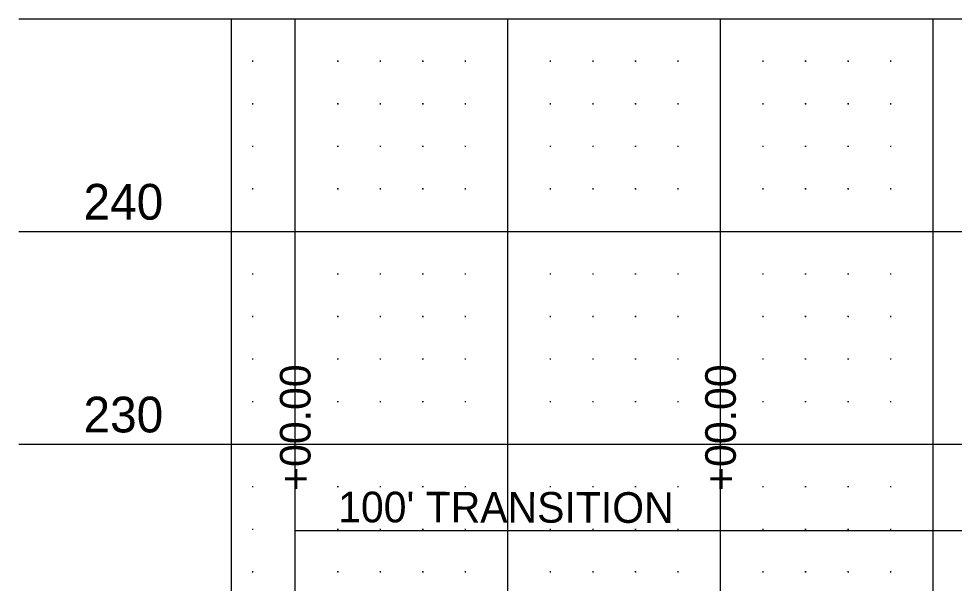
# Model space of a CAD drawing. Extents: x 471 to 2121, y 140 to 650.
# Drawn here: x 471.1 to 691, y 517.3 to 650 of the extents above; entities that cross this region are included whole.
import ezdxf

# ---------------------------------------------------------------- set-up
doc = ezdxf.new("R2010")
doc.units = 0
for name, color, linetype in [('DSN_DRFT_Border Grid', 7, 'Continuous'), ('DSN_RDWY_Prof Annotation', 7, 'Continuous'), ('Transition Dimensions', 7, 'Continuous')]:
    doc.layers.add(name, color=color, linetype=linetype)

msp = doc.modelspace()

# ---------------------------------------------------------------- linework, layer by layer
at = {"layer": 'DSN_DRFT_Border Grid'}
for p, q in [((471.06, 650), (521.06, 650)), ((521.06, 650), (2071.06, 650)), ((521.06, 150), (521.06, 650)), ((521.06, 650), (2071.06, 650)), ((521.06, 150), (521.06, 650)), ((536.06, 150), (536.06, 650)), ((536.06, 150), (536.06, 650)), ((586.06, 150), (586.06, 650)), ((586.06, 150), (586.06, 650)), ((636.06, 150), (636.06, 650)), ((636.06, 150), (636.06, 650)), ((686.06, 150), (686.06, 650)), ((686.06, 150), (686.06, 650)), ((526.18, 640), (525.94, 640)), ((526.18, 640), (525.94, 640)), ((526.06, 640.12), (526.06, 639.88)), ((526.06, 640.12), (526.06, 639.88)), ((546.18, 640), (545.94, 640)), ((546.18, 640), (545.94, 640)), ((546.06, 640.12), (546.06, 639.88)), ((546.06, 640.12), (546.06, 639.88)), ((556.18, 640), (555.94, 640)), ((556.18, 640), (555.94, 640)), ((556.06, 640.12), (556.06, 639.88)), ((556.06, 640.12), (556.06, 639.88)), ((566.18, 640), (565.94, 640)), ((566.18, 640), (565.94, 640)), ((566.06, 640.12), (566.06, 639.88)), ((566.06, 640.12), (566.06, 639.88)), ((576.18, 640), (575.94, 640)), ((576.18, 640), (575.94, 640)), ((576.06, 640.12), (576.06, 639.88)), ((576.06, 640.12), (576.06, 639.88)), ((596.18, 640), (595.94, 640)), ((596.18, 640), (595.94, 640)), ((596.06, 640.12), (596.06, 639.88)), ((596.06, 640.12), (596.06, 639.88)), ((606.18, 640), (605.94, 640)), ((606.18, 640), (605.94, 640)), ((606.06, 640.12), (606.06, 639.88)), ((606.06, 640.12), (606.06, 639.88)), ((616.18, 640), (615.94, 640)), ((616.18, 640), (615.94, 640)), ((616.06, 640.12), (616.06, 639.88)), ((616.06, 640.12), (616.06, 639.88)), ((626.18, 640), (625.94, 640)), ((626.18, 640), (625.94, 640)), ((626.06, 640.12), (626.06, 639.88)), ((626.06, 640.12), (626.06, 639.88)), ((646.18, 640), (645.94, 640)), ((646.18, 640), (645.94, 640)), ((646.06, 640.12), (646.06, 639.88)), ((646.06, 640.12), (646.06, 639.88)), ((656.18, 640), (655.94, 640)), ((656.18, 640), (655.94, 640)), ((656.06, 640.12), (656.06, 639.88)), ((656.06, 640.12), (656.06, 639.88)), ((666.18, 640), (665.94, 640)), ((666.18, 640), (665.94, 640)), ((666.06, 640.12), (666.06, 639.88)), ((666.06, 640.12), (666.06, 639.88)), ((676.18, 640), (675.94, 640)), ((676.18, 640), (675.94, 640)), ((676.06, 640.12), (676.06, 639.88)), ((676.06, 640.12), (676.06, 639.88)), ((526.18, 630), (525.94, 630)), ((526.18, 630), (525.94, 630)), ((526.06, 630.12), (526.06, 629.88)), ((526.06, 630.12), (526.06, 629.88)), ((546.18, 630), (545.94, 630)), ((546.18, 630), (545.94, 630)), ((546.06, 630.12), (546.06, 629.88)), ((546.06, 630.12), (546.06, 629.88)), ((556.18, 630), (555.94, 630)), ((556.18, 630), (555.94, 630)), ((556.06, 630.12), (556.06, 629.88)), ((556.06, 630.12), (556.06, 629.88)), ((566.18, 630), (565.94, 630)), ((566.18, 630), (565.94, 630)), ((566.06, 630.12), (566.06, 629.88)), ((566.06, 630.12), (566.06, 629.88)), ((576.18, 630), (575.94, 630)), ((576.18, 630), (575.94, 630)), ((576.06, 630.12), (576.06, 629.88)), ((576.06, 630.12), (576.06, 629.88)), ((596.18, 630), (595.94, 630)), ((596.18, 630), (595.94, 630)), ((596.06, 630.12), (596.06, 629.88)), ((596.06, 630.12), (596.06, 629.88)), ((606.18, 630), (605.94, 630)), ((606.18, 630), (605.94, 630)), ((606.06, 630.12), (606.06, 629.88)), ((606.06, 630.12), (606.06, 629.88)), ((616.18, 630), (615.94, 630)), ((616.18, 630), (615.94, 630)), ((616.06, 630.12), (616.06, 629.88)), ((616.06, 630.12), (616.06, 629.88)), ((626.18, 630), (625.94, 630)), ((626.18, 630), (625.94, 630)), ((626.06, 630.12), (626.06, 629.88)), ((626.06, 630.12), (626.06, 629.88)), ((646.18, 630), (645.94, 630)), ((646.18, 630), (645.94, 630)), ((646.06, 630.12), (646.06, 629.88)), ((646.06, 630.12), (646.06, 629.88)), ((656.18, 630), (655.94, 630)), ((656.18, 630), (655.94, 630)), ((656.06, 630.12), (656.06, 629.88)), ((656.06, 630.12), (656.06, 629.88)), ((666.18, 630), (665.94, 630)), ((666.18, 630), (665.94, 630)), ((666.06, 630.12), (666.06, 629.88)), ((666.06, 630.12), (666.06, 629.88)), ((676.18, 630), (675.94, 630)), ((676.18, 630), (675.94, 630)), ((676.06, 630.12), (676.06, 629.88)), ((676.06, 630.12), (676.06, 629.88)), ((526.18, 620), (525.94, 620)), ((526.18, 620), (525.94, 620)), ((526.06, 620.12), (526.06, 619.88)), ((526.06, 620.12), (526.06, 619.88)), ((546.18, 620), (545.94, 620)), ((546.18, 620), (545.94, 620)), ((546.06, 620.12), (546.06, 619.88)), ((546.06, 620.12), (546.06, 619.88)), ((556.18, 620), (555.94, 620)), ((556.18, 620), (555.94, 620)), ((556.06, 620.12), (556.06, 619.88)), ((556.06, 620.12), (556.06, 619.88)), ((566.18, 620), (565.94, 620)), ((566.18, 620), (565.94, 620)), ((566.06, 620.12), (566.06, 619.88)), ((566.06, 620.12), (566.06, 619.88)), ((576.18, 620), (575.94, 620)), ((576.18, 620), (575.94, 620)), ((576.06, 620.12), (576.06, 619.88)), ((576.06, 620.12), (576.06, 619.88)), ((596.18, 620), (595.94, 620)), ((596.18, 620), (595.94, 620)), ((596.06, 620.12), (596.06, 619.88)), ((596.06, 620.12), (596.06, 619.88)), ((606.18, 620), (605.94, 620)), ((606.18, 620), (605.94, 620)), ((606.06, 620.12), (606.06, 619.88)), ((606.06, 620.12), (606.06, 619.88)), ((616.18, 620), (615.94, 620)), ((616.18, 620), (615.94, 620)), ((616.06, 620.12), (616.06, 619.88)), ((616.06, 620.12), (616.06, 619.88)), ((626.18, 620), (625.94, 620)), ((626.18, 620), (625.94, 620)), ((626.06, 620.12), (626.06, 619.88)), ((626.06, 620.12), (626.06, 619.88)), ((646.18, 620), (645.94, 620)), ((646.18, 620), (645.94, 620)), ((646.06, 620.12), (646.06, 619.88)), ((646.06, 620.12), (646.06, 619.88)), ((656.18, 620), (655.94, 620)), ((656.18, 620), (655.94, 620)), ((656.06, 620.12), (656.06, 619.88)), ((656.06, 620.12), (656.06, 619.88)), ((666.18, 620), (665.94, 620)), ((666.18, 620), (665.94, 620)), ((666.06, 620.12), (666.06, 619.88)), ((666.06, 620.12), (666.06, 619.88)), ((676.18, 620), (675.94, 620)), ((676.18, 620), (675.94, 620)), ((676.06, 620.12), (676.06, 619.88)), ((676.06, 620.12), (676.06, 619.88)), ((526.18, 610), (525.94, 610)), ((526.18, 610), (525.94, 610)), ((526.06, 610.12), (526.06, 609.88)), ((526.06, 610.12), (526.06, 609.88)), ((546.18, 610), (545.94, 610)), ((546.18, 610), (545.94, 610)), ((546.06, 610.12), (546.06, 609.88)), ((546.06, 610.12), (546.06, 609.88)), ((556.18, 610), (555.94, 610)), ((556.18, 610), (555.94, 610)), ((556.06, 610.12), (556.06, 609.88)), ((556.06, 610.12), (556.06, 609.88)), ((566.18, 610), (565.94, 610)), ((566.18, 610), (565.94, 610)), ((566.06, 610.12), (566.06, 609.88)), ((566.06, 610.12), (566.06, 609.88)), ((576.18, 610), (575.94, 610)), ((576.18, 610), (575.94, 610)), ((576.06, 610.12), (576.06, 609.88)), ((576.06, 610.12), (576.06, 609.88)), ((596.18, 610), (595.94, 610)), ((596.18, 610), (595.94, 610)), ((596.06, 610.12), (596.06, 609.88)), ((596.06, 610.12), (596.06, 609.88)), ((606.18, 610), (605.94, 610)), ((606.18, 610), (605.94, 610)), ((606.06, 610.12), (606.06, 609.88)), ((606.06, 610.12), (606.06, 609.88)), ((616.18, 610), (615.94, 610)), ((616.18, 610), (615.94, 610)), ((616.06, 610.12), (616.06, 609.88)), ((616.06, 610.12), (616.06, 609.88)), ((626.18, 610), (625.94, 610)), ((626.18, 610), (625.94, 610)), ((626.06, 610.12), (626.06, 609.88)), ((626.06, 610.12), (626.06, 609.88)), ((646.18, 610), (645.94, 610)), ((646.18, 610), (645.94, 610)), ((646.06, 610.12), (646.06, 609.88)), ((646.06, 610.12), (646.06, 609.88)), ((656.18, 610), (655.94, 610)), ((656.18, 610), (655.94, 610)), ((656.06, 610.12), (656.06, 609.88)), ((656.06, 610.12), (656.06, 609.88)), ((666.18, 610), (665.94, 610)), ((666.18, 610), (665.94, 610)), ((666.06, 610.12), (666.06, 609.88)), ((666.06, 610.12), (666.06, 609.88)), ((676.18, 610), (675.94, 610)), ((676.18, 610), (675.94, 610)), ((676.06, 610.12), (676.06, 609.88)), ((676.06, 610.12), (676.06, 609.88)), ((471.06, 600), (521.06, 600)), ((521.06, 600), (2071.06, 600)), ((521.06, 600), (2071.06, 600)), ((526.18, 590), (525.94, 590)), ((526.18, 590), (525.94, 590)), ((526.06, 590.12), (526.06, 589.88)), ((526.06, 590.12), (526.06, 589.88)), ((546.18, 590), (545.94, 590)), ((546.18, 590), (545.94, 590)), ((546.06, 590.12), (546.06, 589.88)), ((546.06, 590.12), (546.06, 589.88)), ((556.18, 590), (555.94, 590)), ((556.18, 590), (555.94, 590)), ((556.06, 590.12), (556.06, 589.88)), ((556.06, 590.12), (556.06, 589.88)), ((566.18, 590), (565.94, 590)), ((566.18, 590), (565.94, 590)), ((566.06, 590.12), (566.06, 589.88)), ((566.06, 590.12), (566.06, 589.88)), ((576.18, 590), (575.94, 590)), ((576.18, 590), (575.94, 590)), ((576.06, 590.12), (576.06, 589.88)), ((576.06, 590.12), (576.06, 589.88)), ((596.18, 590), (595.94, 590)), ((596.18, 590), (595.94, 590)), ((596.06, 590.12), (596.06, 589.88)), ((596.06, 590.12), (596.06, 589.88)), ((606.18, 590), (605.94, 590)), ((606.18, 590), (605.94, 590)), ((606.06, 590.12), (606.06, 589.88)), ((606.06, 590.12), (606.06, 589.88)), ((616.18, 590), (615.94, 590)), ((616.18, 590), (615.94, 590)), ((616.06, 590.12), (616.06, 589.88)), ((616.06, 590.12), (616.06, 589.88)), ((626.18, 590), (625.94, 590)), ((626.18, 590), (625.94, 590)), ((626.06, 590.12), (626.06, 589.88)), ((626.06, 590.12), (626.06, 589.88)), ((646.18, 590), (645.94, 590)), ((646.18, 590), (645.94, 590)), ((646.06, 590.12), (646.06, 589.88)), ((646.06, 590.12), (646.06, 589.88)), ((656.18, 590), (655.94, 590)), ((656.18, 590), (655.94, 590)), ((656.06, 590.12), (656.06, 589.88)), ((656.06, 590.12), (656.06, 589.88)), ((666.18, 590), (665.94, 590)), ((666.18, 590), (665.94, 590)), ((666.06, 590.12), (666.06, 589.88)), ((666.06, 590.12), (666.06, 589.88)), ((676.18, 590), (675.94, 590)), ((676.18, 590), (675.94, 590)), ((676.06, 590.12), (676.06, 589.88)), ((676.06, 590.12), (676.06, 589.88)), ((526.18, 580), (525.94, 580)), ((526.18, 580), (525.94, 580)), ((526.06, 580.12), (526.06, 579.88)), ((526.06, 580.12), (526.06, 579.88)), ((546.18, 580), (545.94, 580)), ((546.18, 580), (545.94, 580)), ((546.06, 580.12), (546.06, 579.88)), ((546.06, 580.12), (546.06, 579.88)), ((556.18, 580), (555.94, 580)), ((556.18, 580), (555.94, 580)), ((556.06, 580.12), (556.06, 579.88)), ((556.06, 580.12), (556.06, 579.88)), ((566.18, 580), (565.94, 580)), ((566.18, 580), (565.94, 580)), ((566.06, 580.12), (566.06, 579.88)), ((566.06, 580.12), (566.06, 579.88)), ((576.18, 580), (575.94, 580)), ((576.18, 580), (575.94, 580)), ((576.06, 580.12), (576.06, 579.88)), ((576.06, 580.12), (576.06, 579.88)), ((596.18, 580), (595.94, 580)), ((596.18, 580), (595.94, 580)), ((596.06, 580.12), (596.06, 579.88)), ((596.06, 580.12), (596.06, 579.88)), ((606.18, 580), (605.94, 580)), ((606.18, 580), (605.94, 580)), ((606.06, 580.12), (606.06, 579.88)), ((606.06, 580.12), (606.06, 579.88)), ((616.18, 580), (615.94, 580)), ((616.18, 580), (615.94, 580)), ((616.06, 580.12), (616.06, 579.88)), ((616.06, 580.12), (616.06, 579.88)), ((626.18, 580), (625.94, 580)), ((626.18, 580), (625.94, 580)), ((626.06, 580.12), (626.06, 579.88)), ((626.06, 580.12), (626.06, 579.88)), ((646.18, 580), (645.94, 580)), ((646.18, 580), (645.94, 580)), ((646.06, 580.12), (646.06, 579.88)), ((646.06, 580.12), (646.06, 579.88)), ((656.18, 580), (655.94, 580)), ((656.18, 580), (655.94, 580)), ((656.06, 580.12), (656.06, 579.88)), ((656.06, 580.12), (656.06, 579.88)), ((666.18, 580), (665.94, 580)), ((666.18, 580), (665.94, 580)), ((666.06, 580.12), (666.06, 579.88)), ((666.06, 580.12), (666.06, 579.88)), ((676.18, 580), (675.94, 580)), ((676.18, 580), (675.94, 580)), ((676.06, 580.12), (676.06, 579.88)), ((676.06, 580.12), (676.06, 579.88)), ((526.18, 570), (525.94, 570)), ((526.18, 570), (525.94, 570)), ((526.06, 570.12), (526.06, 569.88)), ((526.06, 570.12), (526.06, 569.88)), ((546.18, 570), (545.94, 570)), ((546.18, 570), (545.94, 570)), ((546.06, 570.12), (546.06, 569.88)), ((546.06, 570.12), (546.06, 569.88)), ((556.18, 570), (555.94, 570)), ((556.18, 570), (555.94, 570)), ((556.06, 570.12), (556.06, 569.88)), ((556.06, 570.12), (556.06, 569.88)), ((566.18, 570), (565.94, 570)), ((566.18, 570), (565.94, 570)), ((566.06, 570.12), (566.06, 569.88)), ((566.06, 570.12), (566.06, 569.88)), ((576.18, 570), (575.94, 570)), ((576.18, 570), (575.94, 570)), ((576.06, 570.12), (576.06, 569.88)), ((576.06, 570.12), (576.06, 569.88)), ((596.18, 570), (595.94, 570)), ((596.18, 570), (595.94, 570)), ((596.06, 570.12), (596.06, 569.88)), ((596.06, 570.12), (596.06, 569.88)), ((606.18, 570), (605.94, 570)), ((606.18, 570), (605.94, 570)), ((606.06, 570.12), (606.06, 569.88)), ((606.06, 570.12), (606.06, 569.88)), ((616.18, 570), (615.94, 570)), ((616.18, 570), (615.94, 570)), ((616.06, 570.12), (616.06, 569.88)), ((616.06, 570.12), (616.06, 569.88)), ((626.18, 570), (625.94, 570)), ((626.18, 570), (625.94, 570)), ((626.06, 570.12), (626.06, 569.88)), ((626.06, 570.12), (626.06, 569.88)), ((646.18, 570), (645.94, 570)), ((646.18, 570), (645.94, 570)), ((646.06, 570.12), (646.06, 569.88)), ((646.06, 570.12), (646.06, 569.88)), ((656.18, 570), (655.94, 570)), ((656.18, 570), (655.94, 570)), ((656.06, 570.12), (656.06, 569.88)), ((656.06, 570.12), (656.06, 569.88)), ((666.18, 570), (665.94, 570)), ((666.18, 570), (665.94, 570)), ((666.06, 570.12), (666.06, 569.88)), ((666.06, 570.12), (666.06, 569.88)), ((676.18, 570), (675.94, 570)), ((676.18, 570), (675.94, 570)), ((676.06, 570.12), (676.06, 569.88)), ((676.06, 570.12), (676.06, 569.88)), ((526.18, 560), (525.94, 560)), ((526.18, 560), (525.94, 560)), ((526.06, 560.12), (526.06, 559.88)), ((526.06, 560.12), (526.06, 559.88)), ((546.18, 560), (545.94, 560)), ((546.18, 560), (545.94, 560)), ((546.06, 560.12), (546.06, 559.88)), ((546.06, 560.12), (546.06, 559.88)), ((556.18, 560), (555.94, 560)), ((556.18, 560), (555.94, 560)), ((556.06, 560.12), (556.06, 559.88)), ((556.06, 560.12), (556.06, 559.88)), ((566.18, 560), (565.94, 560)), ((566.18, 560), (565.94, 560)), ((566.06, 560.12), (566.06, 559.88)), ((566.06, 560.12), (566.06, 559.88)), ((576.18, 560), (575.94, 560)), ((576.18, 560), (575.94, 560)), ((576.06, 560.12), (576.06, 559.88)), ((576.06, 560.12), (576.06, 559.88)), ((596.18, 560), (595.94, 560)), ((596.18, 560), (595.94, 560)), ((596.06, 560.12), (596.06, 559.88)), ((596.06, 560.12), (596.06, 559.88)), ((606.18, 560), (605.94, 560)), ((606.18, 560), (605.94, 560)), ((606.06, 560.12), (606.06, 559.88)), ((606.06, 560.12), (606.06, 559.88)), ((616.18, 560), (615.94, 560)), ((616.18, 560), (615.94, 560)), ((616.06, 560.12), (616.06, 559.88)), ((616.06, 560.12), (616.06, 559.88)), ((626.18, 560), (625.94, 560)), ((626.18, 560), (625.94, 560)), ((626.06, 560.12), (626.06, 559.88)), ((626.06, 560.12), (626.06, 559.88)), ((646.18, 560), (645.94, 560)), ((646.18, 560), (645.94, 560)), ((646.06, 560.12), (646.06, 559.88)), ((646.06, 560.12), (646.06, 559.88)), ((656.18, 560), (655.94, 560)), ((656.18, 560), (655.94, 560)), ((656.06, 560.12), (656.06, 559.88)), ((656.06, 560.12), (656.06, 559.88)), ((666.18, 560), (665.94, 560)), ((666.18, 560), (665.94, 560)), ((666.06, 560.12), (666.06, 559.88)), ((666.06, 560.12), (666.06, 559.88)), ((676.18, 560), (675.94, 560)), ((676.18, 560), (675.94, 560)), ((676.06, 560.12), (676.06, 559.88)), ((676.06, 560.12), (676.06, 559.88)), ((471.06, 550), (521.06, 550)), ((521.06, 550), (2071.06, 550)), ((521.06, 550), (2071.06, 550)), ((526.18, 540), (525.94, 540)), ((526.18, 540), (525.94, 540)), ((526.06, 540.12), (526.06, 539.88)), ((526.06, 540.12), (526.06, 539.88)), ((546.18, 540), (545.94, 540)), ((546.18, 540), (545.94, 540)), ((546.06, 540.12), (546.06, 539.88)), ((546.06, 540.12), (546.06, 539.88)), ((556.18, 540), (555.94, 540)), ((556.18, 540), (555.94, 540)), ((556.06, 540.12), (556.06, 539.88)), ((556.06, 540.12), (556.06, 539.88)), ((566.18, 540), (565.94, 540)), ((566.18, 540), (565.94, 540)), ((566.06, 540.12), (566.06, 539.88)), ((566.06, 540.12), (566.06, 539.88)), ((576.18, 540), (575.94, 540)), ((576.18, 540), (575.94, 540)), ((576.06, 540.12), (576.06, 539.88)), ((576.06, 540.12), (576.06, 539.88)), ((596.18, 540), (595.94, 540)), ((596.18, 540), (595.94, 540)), ((596.06, 540.12), (596.06, 539.88)), ((596.06, 540.12), (596.06, 539.88)), ((606.18, 540), (605.94, 540)), ((606.18, 540), (605.94, 540)), ((606.06, 540.12), (606.06, 539.88)), ((606.06, 540.12), (606.06, 539.88)), ((616.18, 540), (615.94, 540)), ((616.18, 540), (615.94, 540)), ((616.06, 540.12), (616.06, 539.88)), ((616.06, 540.12), (616.06, 539.88)), ((626.18, 540), (625.94, 540)), ((626.18, 540), (625.94, 540)), ((626.06, 540.12), (626.06, 539.88)), ((626.06, 540.12), (626.06, 539.88)), ((646.18, 540), (645.94, 540)), ((646.18, 540), (645.94, 540)), ((646.06, 540.12), (646.06, 539.88)), ((646.06, 540.12), (646.06, 539.88)), ((656.18, 540), (655.94, 540)), ((656.18, 540), (655.94, 540)), ((656.06, 540.12), (656.06, 539.88)), ((656.06, 540.12), (656.06, 539.88)), ((666.18, 540), (665.94, 540)), ((666.18, 540), (665.94, 540)), ((666.06, 540.12), (666.06, 539.88)), ((666.06, 540.12), (666.06, 539.88)), ((676.18, 540), (675.94, 540)), ((676.18, 540), (675.94, 540)), ((676.06, 540.12), (676.06, 539.88)), ((676.06, 540.12), (676.06, 539.88)), ((526.18, 530), (525.94, 530)), ((526.18, 530), (525.94, 530)), ((526.06, 530.12), (526.06, 529.88)), ((526.06, 530.12), (526.06, 529.88)), ((546.18, 530), (545.94, 530)), ((546.18, 530), (545.94, 530)), ((546.06, 530.12), (546.06, 529.88)), ((546.06, 530.12), (546.06, 529.88)), ((556.18, 530), (555.94, 530)), ((556.18, 530), (555.94, 530)), ((556.06, 530.12), (556.06, 529.88)), ((556.06, 530.12), (556.06, 529.88)), ((566.18, 530), (565.94, 530)), ((566.18, 530), (565.94, 530)), ((566.06, 530.12), (566.06, 529.88)), ((566.06, 530.12), (566.06, 529.88)), ((576.18, 530), (575.94, 530)), ((576.18, 530), (575.94, 530)), ((576.06, 530.12), (576.06, 529.88)), ((576.06, 530.12), (576.06, 529.88)), ((596.18, 530), (595.94, 530)), ((596.18, 530), (595.94, 530)), ((596.06, 530.12), (596.06, 529.88)), ((596.06, 530.12), (596.06, 529.88)), ((606.18, 530), (605.94, 530)), ((606.18, 530), (605.94, 530)), ((606.06, 530.12), (606.06, 529.88)), ((606.06, 530.12), (606.06, 529.88)), ((616.18, 530), (615.94, 530)), ((616.18, 530), (615.94, 530)), ((616.06, 530.12), (616.06, 529.88)), ((616.06, 530.12), (616.06, 529.88)), ((626.18, 530), (625.94, 530)), ((626.18, 530), (625.94, 530)), ((626.06, 530.12), (626.06, 529.88)), ((626.06, 530.12), (626.06, 529.88)), ((646.18, 530), (645.94, 530)), ((646.18, 530), (645.94, 530)), ((646.06, 530.12), (646.06, 529.88)), ((646.06, 530.12), (646.06, 529.88)), ((656.18, 530), (655.94, 530)), ((656.18, 530), (655.94, 530)), ((656.06, 530.12), (656.06, 529.88)), ((656.06, 530.12), (656.06, 529.88)), ((666.18, 530), (665.94, 530)), ((666.18, 530), (665.94, 530)), ((666.06, 530.12), (666.06, 529.88)), ((666.06, 530.12), (666.06, 529.88)), ((676.18, 530), (675.94, 530)), ((676.18, 530), (675.94, 530)), ((676.06, 530.12), (676.06, 529.88)), ((676.06, 530.12), (676.06, 529.88)), ((526.18, 520), (525.94, 520)), ((526.18, 520), (525.94, 520)), ((526.06, 520.12), (526.06, 519.88)), ((526.06, 520.12), (526.06, 519.88)), ((546.18, 520), (545.94, 520)), ((546.18, 520), (545.94, 520)), ((546.06, 520.12), (546.06, 519.88)), ((546.06, 520.12), (546.06, 519.88)), ((556.18, 520), (555.94, 520)), ((556.18, 520), (555.94, 520)), ((556.06, 520.12), (556.06, 519.88)), ((556.06, 520.12), (556.06, 519.88)), ((566.18, 520), (565.94, 520)), ((566.18, 520), (565.94, 520)), ((566.06, 520.12), (566.06, 519.88)), ((566.06, 520.12), (566.06, 519.88)), ((576.18, 520), (575.94, 520)), ((576.18, 520), (575.94, 520)), ((576.06, 520.12), (576.06, 519.88)), ((576.06, 520.12), (576.06, 519.88)), ((596.18, 520), (595.94, 520)), ((596.18, 520), (595.94, 520)), ((596.06, 520.12), (596.06, 519.88)), ((596.06, 520.12), (596.06, 519.88)), ((606.18, 520), (605.94, 520)), ((606.18, 520), (605.94, 520)), ((606.06, 520.12), (606.06, 519.88)), ((606.06, 520.12), (606.06, 519.88)), ((616.18, 520), (615.94, 520)), ((616.18, 520), (615.94, 520)), ((616.06, 520.12), (616.06, 519.88)), ((616.06, 520.12), (616.06, 519.88)), ((626.18, 520), (625.94, 520)), ((626.18, 520), (625.94, 520)), ((626.06, 520.12), (626.06, 519.88)), ((626.06, 520.12), (626.06, 519.88)), ((646.18, 520), (645.94, 520)), ((646.18, 520), (645.94, 520)), ((646.06, 520.12), (646.06, 519.88)), ((646.06, 520.12), (646.06, 519.88)), ((656.18, 520), (655.94, 520)), ((656.18, 520), (655.94, 520)), ((656.06, 520.12), (656.06, 519.88)), ((656.06, 520.12), (656.06, 519.88)), ((666.18, 520), (665.94, 520)), ((666.18, 520), (665.94, 520)), ((666.06, 520.12), (666.06, 519.88)), ((666.06, 520.12), (666.06, 519.88)), ((676.18, 520), (675.94, 520)), ((676.18, 520), (675.94, 520)), ((676.06, 520.12), (676.06, 519.88)), ((676.06, 520.12), (676.06, 519.88))]:
    msp.add_line(p, q, dxfattribs=at)
at = {"layer": 'Transition Dimensions'}
for p, q in [((536.06, 520.12), (536.06, 539.38)), ((636.06, 520.12), (636.06, 539.38)), ((536.06, 529.75), (1956.06, 529.75))]:
    msp.add_line(p, q, dxfattribs=at)

# ---------------------------------------------------------------- texts
at = {"layer": 'DSN_RDWY_Prof Annotation'}
for s, p in [('240', (486.3, 602.78)), ('240', (486.3, 602.78)), ('230', (486.3, 552.78)), ('230', (486.3, 552.78))]:
    msp.add_text(s, height=8.4, dxfattribs=at).set_placement(p)
at = {"layer": 'Transition Dimensions'}
for s, rotation, p in [('+00.00', 90.0268, (539.69, 539.05)), ('+00.00', 90.0268, (639.69, 539.05)), ("100' TRANSITION", 359.8866, (546.17, 531.67))]:
    msp.add_text(s, height=7.2, rotation=rotation, dxfattribs=at).set_placement(p)

doc.saveas('drawing.dxf')
